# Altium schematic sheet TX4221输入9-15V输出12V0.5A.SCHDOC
size A4; SheetNumber: 0; SheetTotal: 0
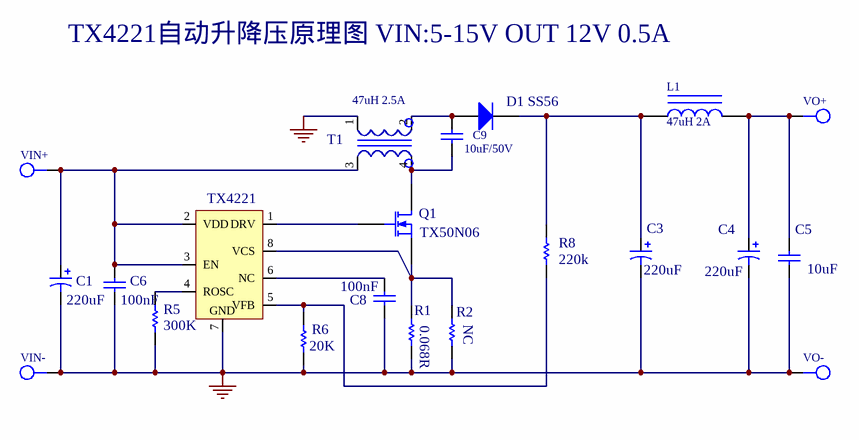
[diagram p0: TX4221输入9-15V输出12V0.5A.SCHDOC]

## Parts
C1  (no value)  [C8*12]
C3  (no value)  [C10*16]
C4  (no value)  [C10*16]
C5  (no value)  [r1206]
C6  (no value)  [r0805]
C8  (no value)  [r0805]
C9  10uF/50V  [C6.3*2.5]
D1_SS56  (no value)  [SMB]
L1  47uH 2A
Q1  40N06  [to252]  (value not drawn)
R1  (no value)  [r1206]
R2  (no value)  [r1206]
R5  (no value)  [r0805]
R6  (no value)  [r0805]
R8  (no value)  [r0805]
T1  (no value)
TX4221  (no value)
VIN+  *  [P]  (value not drawn)
VIN-  *  [P]  (value not drawn)
VO+  (no value)  [P]
VO-  *  [P]  (value not drawn)

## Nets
GND: C1.2 C3.2 C4.2 C5.1 C6.1 C8.1 R1.2 R2.2 R5.1 R6.2 T1.1 TX4221.7 VIN-.P VO-.P
NetC1_1: C1.1 C6.2 T1.3 TX4221.2(VDD) TX4221.3(EN) VIN+.P
NetC3_1: C3.1 D1_SS56.2(K) L1.1 R8.1
NetC4_1: C4.1 C5.2 L1.2 VO+.P
NetC8_2: C8.2 TX4221.6(NC)
NetC9_1: C9.1 D1_SS56.1(A) T1.2
NetC9_2: C9.2 Q1.2(D) T1.4
NetQ1_1: Q1.1(G) TX4221.1(DRV)
NetQ1_3: Q1.3(S) R1.1 R2.1 TX4221.8(VCS)
NetR5_2: R5.2 TX4221.4(ROSC)
NetR6_1: R6.1 R8.2 TX4221.5(VFB)

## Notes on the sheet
- TX4221自动升降压原理图 VIN:5-15V OUT 12V 0.5A
- (near T1) 47uH 2.5A
- (near C8) 100nF
- (near Q1) TX50N06
- (near R8) 220k
- (near C3) 220uF
- (near C4) 220uF
- (near C5) 10uF
- 220uF
- (near R5) 100nF
- 300K
- (near R6) 20K
- (near R1) 0.068R
- (near R2) NC

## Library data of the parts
C1 C3 C4 = Cap Pol1: Polarized Capacitor (Radial)
C5 C6 C8 C9 = Cap: Capacitor
D1_SS56 = Diode: Default Diode
L1 = L
Q1 = MOSFET-N: N-Channel MOSFET
R1 R2 R5 R6 R8 = Res1: Resistor
T1 = T200-1
TX4221 = Component_1
VIN+ VIN- VO+ VO- = P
